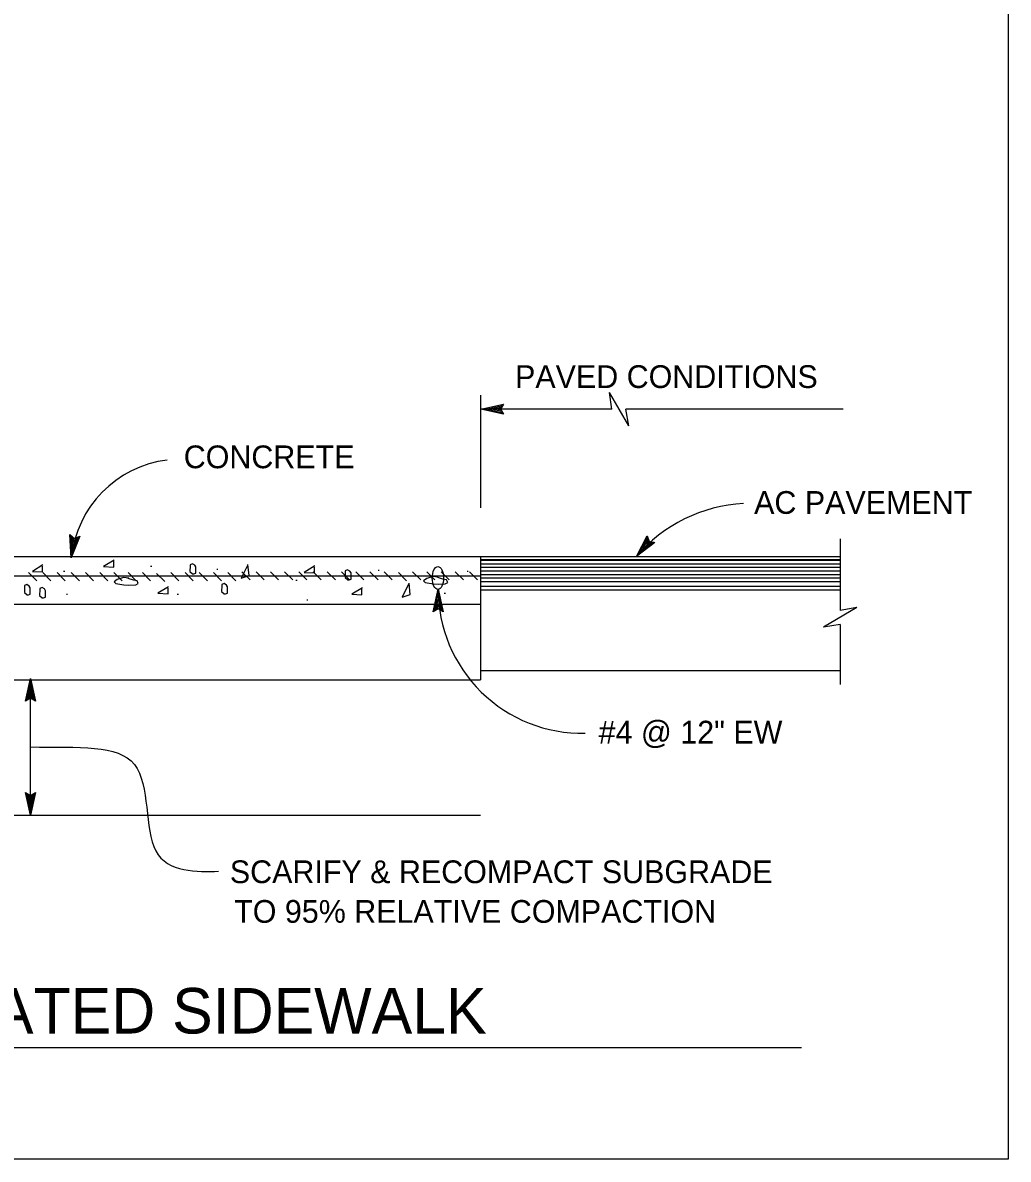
# Model space of a CAD drawing. Extents: x 6710407 to 6714861, y 1868090 to 1871317.
# Drawn here: x 6712967.7 to 6713227.5, y 1869155.1 to 1869454.7 of the extents above; entities that cross this region are included whole.
import ezdxf

# ---------------------------------------------------------------- set-up
doc = ezdxf.new("R2010")
doc.units = 0
for name, color, linetype in [('G-MARK', 7, 'Continuous'), ('G-TEXT', 7, 'Continuous'), ('G-TTLB-VIEW', 7, 'Continuous'), ('Nongeo Data(60)', 7, 'Continuous'), ('Sndwall Anno(59)', 7, 'Continuous')]:
    doc.layers.add(name, color=color, linetype=linetype)

# ---------------------------------------------------------------- blocks, each defined once
blk = doc.blocks.new('SHORTN')
at = {"layer": 'Sndwall Anno(59)'}
for p, q in [((-0.00193, 0), (-0.00259, 0.00447)), ((0.00264, -0.00447), (-0.00259, 0.00447)), ((-0.00193, 0), (-0.00193, 0)), ((0.00264, -0.00447), (0.00183, 0)), ((0.00183, 0), (0.00183, 0))]:
    blk.add_line(p, q, dxfattribs=at)
blk = doc.blocks.new('LOOP')
at = {"layer": 'Sndwall Anno(59)'}
blk.add_ellipse((0.00002, 0.00002), major_axis=(0.00308, -0.00007), ratio=0.490684, dxfattribs=at)

msp = doc.modelspace()

# ---------------------------------------------------------------- linework, layer by layer
at = {"layer": 'G-MARK'}
for p, q in [((6713088.47, 1869326.79), (6713088.47, 1869356.53)), ((6713123, 1869352.79), (6713088.47, 1869352.79)), ((6713184.02, 1869352.79), (6713126.7, 1869352.79)), ((6712969.71, 1869245.76), (6712969.71, 1869281.8)), ((6712923.4, 1869245.76), (6713088.4, 1869245.76))]:
    msp.add_line(p, q, dxfattribs=at)
for centre, radius, start, end in [((6713009.33, 1869310.62), 29, 97.063, 174.092), ((6713159.61, 1869288.53), 39.43, 92.734, 139.8525), ((6713115.21, 1869305.37), 38.01, 179.9283, 271.142)]:
    msp.add_arc(centre, radius, start, end, dxfattribs=at)
msp.add_open_spline([(6712969.71, 1869263.78), (6712982.59, 1869263.58), (6713003.1, 1869265.44), (6712997.91, 1869230.41), (6713013.81, 1869230.84), (6713019.3, 1869230.99)], degree=3, dxfattribs=at)
at = {"layer": 'G-TEXT'}
for p, q in [((6713088.47, 1869352.79), (6713094.47, 1869354.12)), ((6713094.47, 1869351.46), (6713088.47, 1869352.79)), ((6713088.47, 1869352.79), (6713088.47, 1869352.79)), ((6713094.25, 1869351.81), (6713089.85, 1869352.79)), ((6713089.86, 1869352.8), (6713094.23, 1869353.77)), ((6713091.23, 1869352.79), (6713094.06, 1869353.42)), ((6713094.02, 1869352.17), (6713091.23, 1869352.79)), ((6713092.61, 1869352.79), (6713093.82, 1869353.06)), ((6713093.84, 1869352.52), (6713092.61, 1869352.79)), ((6713094.47, 1869354.12), (6713093.67, 1869352.79)), ((6713093.67, 1869352.79), (6713094.47, 1869351.46)), ((6713094.47, 1869354.12), (6713094.47, 1869354.12)), ((6713094.47, 1869351.46), (6713094.47, 1869351.46)), ((6712980.49, 1869313.6), (6712980.13, 1869319.74)), ((6712980.13, 1869319.74), (6712980.13, 1869319.74)), ((6712980.13, 1869319.74), (6712981.32, 1869318.74)), ((6712980.71, 1869314.98), (6712980.45, 1869319.45)), ((6712982.77, 1869319.31), (6712980.49, 1869313.6)), ((6712982.38, 1869319.16), (6712980.71, 1869314.96)), ((6712980.93, 1869316.33), (6712980.77, 1869319.22)), ((6712981.99, 1869318.98), (6712980.93, 1869316.33)), ((6712981.16, 1869317.69), (6712981.08, 1869318.93)), ((6712981.62, 1869318.86), (6712981.16, 1869317.69)), ((6712981.32, 1869318.74), (6712982.77, 1869319.31)), ((6712982.77, 1869319.31), (6712982.77, 1869319.31)), ((6713129.47, 1869313.95), (6713132.32, 1869319.4)), ((6713130.36, 1869315.02), (6713132.44, 1869318.98)), ((6713132.32, 1869319.4), (6713132.32, 1869319.4)), ((6713132.32, 1869319.4), (6713132.82, 1869317.93)), ((6713134.36, 1869317.67), (6713129.47, 1869313.95)), ((6713133.95, 1869317.74), (6713130.36, 1869315.01)), ((6713131.25, 1869316.06), (6713132.59, 1869318.62)), ((6713133.52, 1869317.79), (6713131.25, 1869316.06)), ((6713132.14, 1869317.12), (6713132.72, 1869318.21)), ((6713133.15, 1869317.88), (6713132.14, 1869317.12)), ((6713132.82, 1869317.93), (6713134.36, 1869317.67)), ((6713134.36, 1869317.67), (6713134.36, 1869317.67)), ((6712980.49, 1869313.6), (6712980.49, 1869313.6)), ((6713129.47, 1869313.95), (6713129.47, 1869313.95)), ((6713075.86, 1869299.42), (6713077.21, 1869305.41)), ((6713076.21, 1869299.63), (6713077.2, 1869304.04)), ((6713077.21, 1869305.41), (6713077.21, 1869305.41)), ((6713077.21, 1869305.41), (6713078.53, 1869299.41)), ((6713077.21, 1869304.02), (6713078.17, 1869299.65)), ((6713076.57, 1869299.87), (6713077.2, 1869302.65)), ((6713076.92, 1869300.04), (6713077.2, 1869301.27)), ((6713077.2, 1869302.65), (6713077.82, 1869299.83)), ((6713077.2, 1869301.27), (6713077.46, 1869300.06)), ((6713077.2, 1869300.21), (6713075.86, 1869299.42)), ((6713075.86, 1869299.42), (6713075.86, 1869299.42)), ((6713078.53, 1869299.41), (6713077.2, 1869300.21)), ((6713078.53, 1869299.41), (6713078.53, 1869299.41)), ((6712968.37, 1869275.8), (6712969.71, 1869281.8)), ((6712968.73, 1869276.02), (6712969.71, 1869280.43)), ((6712969.71, 1869281.8), (6712969.71, 1869281.8)), ((6712969.71, 1869281.8), (6712971.04, 1869275.8)), ((6712969.72, 1869280.41), (6712970.68, 1869276.04)), ((6712969.09, 1869276.26), (6712969.71, 1869279.04)), ((6712969.43, 1869276.43), (6712969.71, 1869277.66)), ((6712969.71, 1869279.04), (6712970.34, 1869276.22)), ((6712969.71, 1869277.66), (6712969.98, 1869276.45)), ((6712969.71, 1869276.6), (6712968.37, 1869275.8)), ((6712968.37, 1869275.8), (6712968.37, 1869275.8)), ((6712971.04, 1869275.8), (6712969.71, 1869276.6)), ((6712971.04, 1869275.8), (6712971.04, 1869275.8)), ((6712969.71, 1869245.76), (6712968.38, 1869251.76)), ((6712968.38, 1869251.76), (6712968.38, 1869251.76)), ((6712968.38, 1869251.76), (6712969.71, 1869250.96)), ((6712969.71, 1869247.16), (6712968.74, 1869251.53)), ((6712969.71, 1869248.53), (6712969.09, 1869251.35)), ((6712969.72, 1869249.91), (6712969.45, 1869251.12)), ((6712969.71, 1869250.96), (6712971.05, 1869251.76)), ((6712971.05, 1869251.76), (6712969.71, 1869245.76)), ((6712970.7, 1869251.55), (6712969.71, 1869247.14)), ((6712970.34, 1869251.31), (6712969.71, 1869248.53)), ((6712969.99, 1869251.14), (6712969.72, 1869249.91)), ((6712971.05, 1869251.76), (6712971.05, 1869251.76)), ((6712969.71, 1869245.76), (6712969.71, 1869245.76))]:
    msp.add_line(p, q, dxfattribs=at)
at = {"layer": 'G-TTLB-VIEW'}
msp.add_lwpolyline([(6711433.78, 1870605.06), (6713227.53, 1870605.06), (6713227.53, 1869155.06), (6711433.78, 1869155.06)], close=True, dxfattribs=at)
at = {"layer": 'Nongeo Data(60)'}
for p, q in [((6713183.21, 1869318.66), (6713183.21, 1869299.72)), ((6712923.4, 1869313.95), (6713088.4, 1869313.95)), ((6713088.4, 1869313.95), (6713183.4, 1869313.95)), ((6713088.4, 1869313.95), (6713088.4, 1869281.45)), ((6713088.4, 1869313.2), (6713183.4, 1869313.2)), ((6713088.4, 1869313.01), (6713183.4, 1869313.01)), ((6712978.46, 1869310.09), (6712978.74, 1869310.09)), ((6713001.4, 1869311.4), (6713001.68, 1869311.4)), ((6713018.87, 1869310.61), (6713019.15, 1869310.61)), ((6713027.61, 1869307.79), (6713025.47, 1869309.93)), ((6713031.36, 1869307.79), (6713029.22, 1869309.93)), ((6713035.11, 1869307.79), (6713032.97, 1869309.93)), ((6713038.86, 1869307.79), (6713036.72, 1869309.93)), ((6713042.61, 1869307.79), (6713040.47, 1869309.93)), ((6713046.36, 1869307.79), (6713044.22, 1869309.93)), ((6713050.11, 1869307.79), (6713047.97, 1869309.93)), ((6713053.86, 1869307.79), (6713051.72, 1869309.93)), ((6713057.61, 1869307.79), (6713055.47, 1869309.93)), ((6713061.36, 1869307.79), (6713059.22, 1869309.93)), ((6713061.37, 1869310.35), (6713061.65, 1869310.35)), ((6713065.11, 1869307.79), (6713062.97, 1869309.93)), ((6713072.61, 1869307.79), (6713070.47, 1869309.93)), ((6713076.36, 1869307.79), (6713074.22, 1869309.93)), ((6713080.11, 1869307.79), (6713077.97, 1869309.93)), ((6713083.86, 1869307.79), (6713081.72, 1869309.93)), ((6713084.83, 1869310.09), (6713085.11, 1869310.09)), ((6713087.61, 1869307.79), (6713085.47, 1869309.93)), ((6713088.4, 1869312.08), (6713183.4, 1869312.08)), ((6713088.4, 1869311.14), (6713183.4, 1869311.14)), ((6713088.4, 1869310.2), (6713183.4, 1869310.2)), ((6712923.37, 1869308.86), (6713088.5, 1869308.86)), ((6712971.37, 1869307.59), (6712969.23, 1869309.73)), ((6712975.12, 1869307.59), (6712972.98, 1869309.73)), ((6712978.87, 1869307.59), (6712976.73, 1869309.73)), ((6712982.62, 1869307.59), (6712980.48, 1869309.73)), ((6712986.37, 1869307.59), (6712984.23, 1869309.73)), ((6712990.11, 1869307.59), (6712987.97, 1869309.73)), ((6712993.86, 1869307.59), (6712991.72, 1869309.73)), ((6712997.61, 1869307.59), (6712995.47, 1869309.73)), ((6713001.36, 1869307.59), (6712999.22, 1869309.73)), ((6713005.11, 1869307.39), (6713002.97, 1869309.53)), ((6713008.86, 1869307.59), (6713006.72, 1869309.73)), ((6713012.61, 1869307.59), (6713010.47, 1869309.73)), ((6713016.36, 1869307.59), (6713014.22, 1869309.73)), ((6713020.11, 1869307.59), (6713017.97, 1869309.73)), ((6713023.86, 1869307.59), (6713021.72, 1869309.73)), ((6713039.73, 1869307.74), (6713040.01, 1869307.74)), ((6713068.86, 1869307.59), (6713066.72, 1869309.73)), ((6713088.4, 1869309.26), (6713183.4, 1869309.26)), ((6713088.4, 1869308.33), (6713183.4, 1869308.33)), ((6713088.4, 1869307.39), (6713183.4, 1869307.39)), ((6712979.24, 1869304.09), (6712979.52, 1869304.09)), ((6713008.44, 1869304.09), (6713008.72, 1869304.09)), ((6713078.84, 1869304.35), (6713079.12, 1869304.35)), ((6713088.4, 1869306.14), (6713183.4, 1869306.14)), ((6713088.4, 1869305.2), (6713183.4, 1869305.2)), ((6712923.4, 1869301.45), (6713088.4, 1869301.45)), ((6713042.6, 1869302.52), (6713042.88, 1869302.52)), ((6713183.21, 1869296.02), (6713183.21, 1869280.22)), ((6713088.4, 1869283.95), (6713183.4, 1869283.95)), ((6712923.4, 1869281.45), (6713088.4, 1869281.45)), ((6712969.71, 1869245.76), (6712968.38, 1869251.76)), ((6712968.38, 1869251.76), (6712968.38, 1869251.76)), ((6712968.38, 1869251.76), (6712969.71, 1869250.96)), ((6712969.71, 1869247.16), (6712968.74, 1869251.53)), ((6712969.71, 1869248.53), (6712969.09, 1869251.35)), ((6712969.72, 1869249.91), (6712969.45, 1869251.12)), ((6712969.71, 1869250.96), (6712971.05, 1869251.76)), ((6712971.05, 1869251.76), (6712969.71, 1869245.76)), ((6712970.7, 1869251.55), (6712969.71, 1869247.14)), ((6712970.34, 1869251.31), (6712969.71, 1869248.53)), ((6712969.99, 1869251.14), (6712969.72, 1869249.91)), ((6712971.05, 1869251.76), (6712971.05, 1869251.76)), ((6712969.71, 1869245.76), (6712969.71, 1869245.76)), ((6713173.03, 1869184.48), (6712848.73, 1869184.48))]:
    msp.add_line(p, q, dxfattribs=at)
for points in [[(6712991.79, 1869313.04), (6712988.99, 1869311.32), (6712991.67, 1869311.2), (6712991.67, 1869312.71)], [(6712973.02, 1869311.74), (6712970.22, 1869310.02), (6712972.9, 1869309.9), (6712972.9, 1869311.41)], [(6713011.8, 1869311.52), (6713011.74, 1869309.99), (6713012.46, 1869309.37), (6713012.81, 1869309.37), (6713013.31, 1869309.55), (6713013.31, 1869310.27), (6713013.31, 1869311.23), (6713013.03, 1869311.68), (6713012.41, 1869312.06), (6713011.8, 1869311.79), (6713011.8, 1869311.52), (6713011.8, 1869311.52)], [(6713026.93, 1869311.62), (6713025.25, 1869308.26), (6713027.38, 1869308.93), (6713027.04, 1869311.89)], [(6713044.72, 1869311.48), (6713041.92, 1869309.76), (6713044.6, 1869309.64), (6713044.6, 1869311.15)], [(6713052.73, 1869309.95), (6713052.67, 1869308.42), (6713053.39, 1869307.8), (6713053.74, 1869307.8), (6713054.24, 1869307.98), (6713054.24, 1869308.7), (6713054.24, 1869309.66), (6713053.96, 1869310.11), (6713053.34, 1869310.49), (6713052.73, 1869310.22), (6713052.73, 1869309.95), (6713052.73, 1869309.95)], [(6712995.63, 1869308.29), (6712994.22, 1869308.46), (6712992.6, 1869307.95), (6712991.77, 1869307.33), (6712992.22, 1869306.84), (6712994.35, 1869306.55), (6712995.63, 1869306.44), (6712997.47, 1869306.49), (6712998.15, 1869306.84), (6712997.81, 1869307.56), (6712996.87, 1869307.74), (6712995.52, 1869308.17), (6712995.52, 1869308.17)], [(6713020.14, 1869306.3), (6713020.08, 1869304.77), (6713020.8, 1869304.15), (6713021.15, 1869304.15), (6713021.65, 1869304.33), (6713021.65, 1869305.05), (6713021.65, 1869306.01), (6713021.37, 1869306.46), (6713020.75, 1869306.84), (6713020.14, 1869306.57), (6713020.14, 1869306.3), (6713020.14, 1869306.3)], [(6713069.42, 1869306.66), (6713067.74, 1869303.3), (6713069.87, 1869303.97), (6713069.53, 1869306.93)], [(6713077.23, 1869308.55), (6713075.82, 1869308.72), (6713074.2, 1869308.21), (6713073.37, 1869307.59), (6713073.82, 1869307.1), (6713075.95, 1869306.81), (6713077.23, 1869306.7), (6713079.07, 1869306.75), (6713079.75, 1869307.1), (6713079.41, 1869307.82), (6713078.47, 1869308), (6713077.12, 1869308.43), (6713077.12, 1869308.43)], [(6712968.17, 1869306.04), (6712968.11, 1869304.51), (6712968.83, 1869303.89), (6712969.18, 1869303.89), (6712969.68, 1869304.07), (6712969.68, 1869304.79), (6712969.68, 1869305.75), (6712969.4, 1869306.2), (6712968.78, 1869306.58), (6712968.17, 1869306.31), (6712968.17, 1869306.04), (6712968.17, 1869306.04)], [(6712972.17, 1869305.26), (6712972.11, 1869303.73), (6712972.83, 1869303.11), (6712973.18, 1869303.11), (6712973.68, 1869303.29), (6712973.68, 1869304.01), (6712973.68, 1869304.97), (6712973.4, 1869305.42), (6712972.78, 1869305.8), (6712972.17, 1869305.53), (6712972.17, 1869305.26), (6712972.17, 1869305.26)], [(6713006.13, 1869306), (6713003.33, 1869304.28), (6713006.01, 1869304.16), (6713006.01, 1869305.67)], [(6713057.23, 1869305.74), (6713054.43, 1869304.02), (6713057.11, 1869303.9), (6713057.11, 1869305.41)]]:
    msp.add_lwpolyline(points, dxfattribs=at)

# ---------------------------------------------------------------- block references
at = {"layer": 'G-MARK', "xscale": 984.251968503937, "yscale": 984.251968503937}
msp.add_blockref('SHORTN', (6713124.9, 1869352.8), dxfattribs=at)
at = {"layer": 'Nongeo Data(60)'}
for name, p, xscale, yscale, rotation in [('LOOP', (6713077.17, 1869308.28), 984.223884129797, 984.223883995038, 91.66132957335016), ('SHORTN', (6713183.21, 1869297.93), 984.251968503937, 984.251968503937, 90)]:
    msp.add_blockref(name, p, dxfattribs=dict(at, xscale=xscale, yscale=yscale, rotation=rotation))

# ---------------------------------------------------------------- texts
for s, height, p in [('PAVED CONDITIONS', 6, (6713097.49, 1869358.4)), ('CONCRETE', 6, (6713010.13, 1869337.25)), ('AC PAVEMENT', 6, (6713160.52, 1869325.22)), ('#4 @ 12" EW', 6, (6713119.52, 1869264.67)), ('SCARIFY & RECOMPACT SUBGRADE', 6, (6713022.29, 1869227.86)), ('TO 95% RELATIVE COMPACTION', 6, (6713023.43, 1869217.41)), ('TRAFFIC - RATED SIDEWALK', 12, (6712866.22, 1869188.22))]:
    msp.add_text(s, height=height, dxfattribs=at).set_placement(p)

doc.saveas('drawing.dxf')
